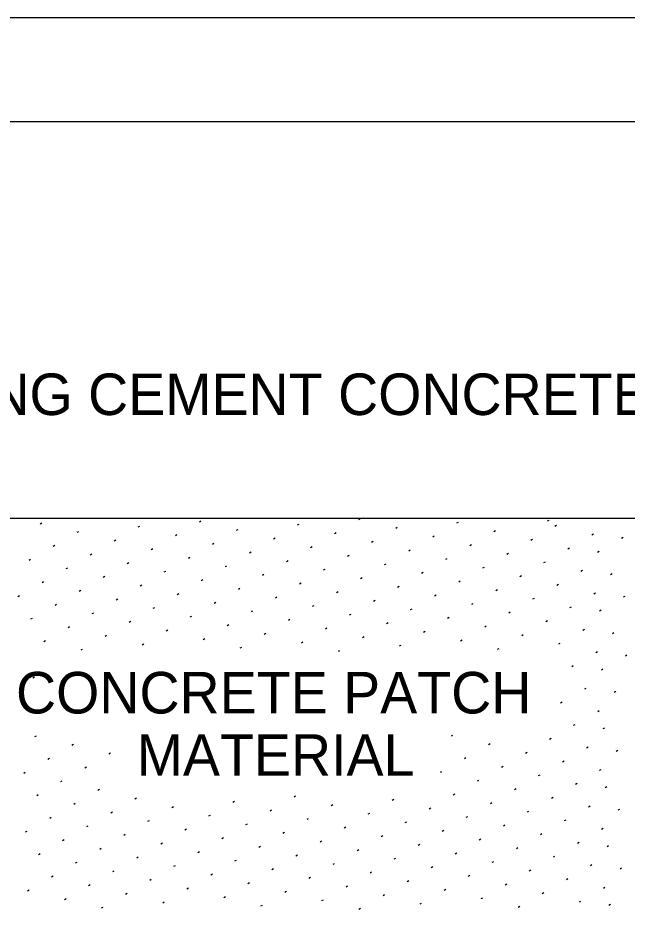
# Model space of a CAD drawing. Extents: x 99862 to 104211, y 98939 to 105076.
# Drawn here: x 102180.3 to 102415, y 104731.9 to 105075.5 of the extents above; entities that cross this region are included whole.
import ezdxf

# ---------------------------------------------------------------- set-up
doc = ezdxf.new("R2010")
doc.units = 0
for name, color, linetype in [('Level 1', 7, 'Continuous'), ('Level 20', 7, 'Continuous'), ('Level 3', 7, 'Continuous')]:
    doc.layers.add(name, color=color, linetype=linetype)

msp = doc.modelspace()

# ---------------------------------------------------------------- linework, layer by layer
at = {"layer": 'Level 1'}
msp.add_line((100264.63, 104882.79), (102495.44, 104882.79), dxfattribs=at)
msp.add_lwpolyline([(99862, 102999.5), (103151, 102999.5), (103151, 105075.5), (99862, 105075.5)], close=True, dxfattribs=at)
msp.add_lwpolyline([(102651.95, 105035.45), (102087.59, 105035.45), (102087.59, 105018.74), (102054.18, 105052.15), (102054.18, 105035.45), (101386.54, 105035.45)], dxfattribs=at)
at = {"layer": 'Level 3'}
for p, q in [((102188.93, 104880.7), (102189.54, 104881.05)), ((102212.46, 104882.74), (102212.56, 104882.79)), ((102226.73, 104879.43), (102227.34, 104879.78)), ((102250.27, 104881.47), (102250.87, 104881.82)), ((102288.07, 104880.21), (102288.68, 104880.56)), ((102311.61, 104882.25), (102312.21, 104882.6)), ((102349.41, 104880.98), (102350.02, 104881.33)), ((102384.34, 104881.75), (102384.95, 104882.1)), ((102387.21, 104879.71), (102387.82, 104880.06)), ((102203.2, 104877.39), (102203.8, 104877.74)), ((102241, 104876.12), (102241.61, 104876.47)), ((102264.54, 104878.16), (102265.14, 104878.51)), ((102302.34, 104876.9), (102302.94, 104877.25)), ((102325.87, 104878.94), (102326.48, 104879.29)), ((102363.68, 104877.67), (102364.28, 104878.02)), ((102401.48, 104876.4), (102402.09, 104876.75)), ((102217.46, 104874.08), (102218.07, 104874.43)), ((102255.27, 104872.81), (102255.87, 104873.16)), ((102278.8, 104874.85), (102279.41, 104875.2)), ((102316.61, 104873.59), (102317.21, 104873.94)), ((102340.14, 104875.63), (102340.75, 104875.98)), ((102354.41, 104872.32), (102355.02, 104872.67)), ((102377.94, 104874.36), (102378.55, 104874.71)), ((102412.88, 104875.13), (102413.48, 104875.48)), ((102193.93, 104872.04), (102194.54, 104872.39)), ((102231.73, 104870.77), (102232.34, 104871.12)), ((102269.54, 104869.5), (102270.14, 104869.85)), ((102293.07, 104871.54), (102293.68, 104871.89)), ((102330.87, 104870.28), (102331.48, 104870.63)), ((102368.68, 104869.01), (102369.28, 104869.36)), ((102392.21, 104871.05), (102392.82, 104871.4)), ((102403.61, 104869.78), (102404.22, 104870.13)), ((102184.66, 104866.69), (102185.27, 104867.04)), ((102208.2, 104868.73), (102208.8, 104869.08)), ((102246, 104867.46), (102246.61, 104867.81)), ((102283.8, 104866.19), (102284.41, 104866.54)), ((102307.34, 104868.24), (102307.94, 104868.59)), ((102345.14, 104866.97), (102345.75, 104867.32)), ((102382.94, 104865.7), (102383.55, 104866.05)), ((102198.93, 104863.38), (102199.54, 104863.73)), ((102222.46, 104865.42), (102223.07, 104865.77)), ((102236.73, 104862.11), (102237.34, 104862.46)), ((102260.27, 104864.15), (102260.87, 104864.5)), ((102298.07, 104862.88), (102298.68, 104863.23)), ((102321.61, 104864.93), (102322.21, 104865.28)), ((102359.41, 104863.66), (102360.02, 104864.01)), ((102397.21, 104862.39), (102397.82, 104862.74)), ((102213.2, 104860.07), (102213.8, 104860.42)), ((102251, 104858.8), (102251.61, 104859.15)), ((102274.54, 104860.84), (102275.14, 104861.19)), ((102312.34, 104859.57), (102312.94, 104859.92)), ((102335.87, 104861.62), (102336.48, 104861.97)), ((102373.68, 104860.35), (102374.28, 104860.7)), ((102408.61, 104861.12), (102409.22, 104861.47)), ((102189.66, 104858.03), (102190.27, 104858.38)), ((102227.46, 104856.76), (102228.07, 104857.11)), ((102265.27, 104855.49), (102265.87, 104855.84)), ((102288.8, 104857.53), (102289.41, 104857.88)), ((102326.61, 104856.27), (102327.21, 104856.62)), ((102350.14, 104858.31), (102350.75, 104858.66)), ((102387.94, 104857.04), (102388.55, 104857.39)), ((102180.39, 104852.68), (102181, 104853.03)), ((102203.93, 104854.72), (102204.54, 104855.07)), ((102241.73, 104853.45), (102242.34, 104853.8)), ((102279.54, 104852.18), (102280.14, 104852.53)), ((102303.07, 104854.22), (102303.68, 104854.57)), ((102340.87, 104852.96), (102341.48, 104853.31)), ((102364.41, 104855), (102365.02, 104855.35)), ((102378.68, 104851.69), (102379.28, 104852.04)), ((102402.21, 104853.73), (102402.82, 104854.08)), ((102413.61, 104852.46), (102414.22, 104852.81)), ((102194.66, 104849.37), (102195.27, 104849.72)), ((102218.2, 104851.41), (102218.8, 104851.76)), ((102256, 104850.14), (102256.61, 104850.49)), ((102293.8, 104848.87), (102294.41, 104849.22)), ((102317.34, 104850.91), (102317.94, 104851.26)), ((102355.14, 104849.65), (102355.75, 104850)), ((102392.94, 104848.38), (102393.55, 104848.73)), ((102208.93, 104846.06), (102209.54, 104846.41)), ((102232.46, 104848.1), (102233.07, 104848.45)), ((102270.27, 104846.83), (102270.87, 104847.18)), ((102308.07, 104845.56), (102308.68, 104845.91)), ((102331.61, 104847.61), (102332.21, 104847.96)), ((102369.41, 104846.34), (102370.02, 104846.69)), ((102404.34, 104847.11), (102404.95, 104847.46)), ((102185.39, 104844.02), (102186, 104844.37)), ((102223.2, 104842.75), (102223.8, 104843.1)), ((102246.73, 104844.79), (102247.34, 104845.14)), ((102261, 104841.48), (102261.61, 104841.83)), ((102284.54, 104843.52), (102285.14, 104843.87)), ((102322.34, 104842.25), (102322.94, 104842.6)), ((102345.87, 104844.3), (102346.48, 104844.65)), ((102383.68, 104843.03), (102384.28, 104843.38)), ((102199.66, 104840.71), (102200.27, 104841.06)), ((102237.46, 104839.44), (102238.07, 104839.79)), ((102275.27, 104838.17), (102275.87, 104838.52)), ((102298.8, 104840.21), (102299.41, 104840.56)), ((102336.61, 104838.94), (102337.21, 104839.29)), ((102360.14, 104840.99), (102360.75, 104841.34)), ((102397.94, 104839.72), (102398.55, 104840.07)), ((102409.34, 104838.45), (102409.95, 104838.8)), ((102190.39, 104835.36), (102191, 104835.71)), ((102213.93, 104837.4), (102214.54, 104837.75)), ((102251.73, 104836.13), (102252.34, 104836.48)), ((102289.54, 104834.86), (102290.14, 104835.21)), ((102313.07, 104836.9), (102313.68, 104837.25)), ((102350.87, 104835.64), (102351.48, 104835.99)), ((102374.41, 104837.68), (102375.02, 104838.03)), ((102204.66, 104832.05), (102205.27, 104832.4)), ((102228.2, 104834.09), (102228.8, 104834.44)), ((102266, 104832.82), (102266.61, 104833.17)), ((102303.8, 104831.55), (102304.41, 104831.9)), ((102327.34, 104833.59), (102327.94, 104833.94)), ((102365.14, 104832.33), (102365.75, 104832.68)), ((102388.68, 104834.37), (102389.28, 104834.72)), ((102402.94, 104831.06), (102403.55, 104831.41)), ((102414.34, 104829.79), (102414.95, 104830.14)), ((102393.68, 104825.71), (102394.28, 104826.06)), ((102405.08, 104824.44), (102405.68, 104824.79)), ((102186.13, 104821.35), (102186.73, 104821.7)), ((102398.68, 104817.05), (102399.28, 104817.4)), ((102410.08, 104815.78), (102410.68, 104816.13)), ((102389.41, 104811.7), (102390.02, 104812.05)), ((102403.68, 104808.39), (102404.28, 104808.74)), ((102394.41, 104803.04), (102395.02, 104803.39)), ((102405.81, 104801.77), (102406.41, 104802.12)), ((102186.86, 104798.68), (102187.46, 104799.03)), ((102347.34, 104798.95), (102347.94, 104799.3)), ((102385.14, 104797.68), (102385.75, 104798.03)), ((102201.13, 104795.37), (102201.73, 104795.72)), ((102361.61, 104795.64), (102362.21, 104795.99)), ((102399.41, 104794.38), (102400.02, 104794.73)), ((102191.86, 104790.02), (102192.46, 104790.37)), ((102215.39, 104792.06), (102216, 104792.41)), ((102352.34, 104790.29), (102352.94, 104790.64)), ((102375.87, 104792.33), (102376.48, 104792.68)), ((102410.81, 104793.11), (102411.41, 104793.46)), ((102206.13, 104786.71), (102206.73, 104787.06)), ((102366.61, 104786.98), (102367.21, 104787.33)), ((102390.14, 104789.02), (102390.75, 104789.37)), ((102182.59, 104784.67), (102183.2, 104785.02)), ((102343.07, 104784.94), (102343.68, 104785.29)), ((102380.87, 104783.67), (102381.48, 104784.02)), ((102404.41, 104785.71), (102405.02, 104786.06)), ((102196.86, 104781.36), (102197.46, 104781.71)), ((102357.34, 104781.63), (102357.94, 104781.98)), ((102395.14, 104780.36), (102395.75, 104780.71)), ((102211.13, 104778.05), (102211.73, 104778.4)), ((102348.07, 104776.28), (102348.68, 104776.63)), ((102371.61, 104778.32), (102372.21, 104778.67)), ((102406.54, 104779.1), (102407.15, 104779.45)), ((102187.59, 104776), (102188.2, 104776.35)), ((102201.86, 104772.7), (102202.46, 104773.05)), ((102225.39, 104774.74), (102226, 104775.09)), ((102263.2, 104773.47), (102263.8, 104773.82)), ((102286.73, 104775.51), (102287.34, 104775.86)), ((102324.54, 104774.24), (102325.14, 104774.59)), ((102362.34, 104772.97), (102362.94, 104773.32)), ((102385.87, 104775.01), (102386.48, 104775.36)), ((102216.13, 104769.39), (102216.73, 104769.74)), ((102239.66, 104771.43), (102240.27, 104771.78)), ((102277.46, 104770.16), (102278.07, 104770.51)), ((102301, 104772.2), (102301.61, 104772.55)), ((102338.8, 104770.93), (102339.41, 104771.28)), ((102376.61, 104769.66), (102377.21, 104770.01)), ((102400.14, 104771.7), (102400.75, 104772.05)), ((102411.54, 104770.44), (102412.15, 104770.79)), ((102192.59, 104767.34), (102193.2, 104767.69)), ((102230.39, 104766.08), (102231, 104766.43)), ((102253.93, 104768.12), (102254.54, 104768.47)), ((102291.73, 104766.85), (102292.34, 104767.2)), ((102315.27, 104768.89), (102315.87, 104769.24)), ((102353.07, 104767.62), (102353.68, 104767.97)), ((102390.87, 104766.35), (102391.48, 104766.7)), ((102206.86, 104764.04), (102207.46, 104764.39)), ((102244.66, 104762.77), (102245.27, 104763.12)), ((102268.2, 104764.81), (102268.8, 104765.16)), ((102306, 104763.54), (102306.61, 104763.89)), ((102329.54, 104765.58), (102330.14, 104765.93)), ((102367.34, 104764.31), (102367.94, 104764.66)), ((102405.14, 104763.04), (102405.75, 104763.39)), ((102183.32, 104761.99), (102183.93, 104762.34)), ((102221.13, 104760.73), (102221.73, 104761.08)), ((102258.93, 104759.46), (102259.54, 104759.81)), ((102282.46, 104761.5), (102283.07, 104761.85)), ((102320.27, 104760.23), (102320.87, 104760.58)), ((102343.8, 104762.27), (102344.41, 104762.62)), ((102358.07, 104758.96), (102358.68, 104759.31)), ((102381.61, 104761), (102382.21, 104761.35)), ((102197.59, 104758.68), (102198.2, 104759.03)), ((102235.39, 104757.42), (102236, 104757.77)), ((102273.2, 104756.15), (102273.8, 104756.5)), ((102296.73, 104758.19), (102297.34, 104758.54)), ((102334.54, 104756.92), (102335.14, 104757.27)), ((102372.34, 104755.65), (102372.94, 104756)), ((102395.87, 104757.69), (102396.48, 104758.04)), ((102407.27, 104756.42), (102407.88, 104756.77)), ((102188.32, 104753.33), (102188.93, 104753.68)), ((102211.86, 104755.37), (102212.46, 104755.72)), ((102226.13, 104752.07), (102226.73, 104752.42)), ((102249.66, 104754.11), (102250.27, 104754.46)), ((102287.46, 104752.84), (102288.07, 104753.19)), ((102311, 104754.88), (102311.61, 104755.23)), ((102348.8, 104753.61), (102349.41, 104753.96)), ((102386.61, 104752.34), (102387.21, 104752.69)), ((102202.59, 104750.02), (102203.2, 104750.37)), ((102240.39, 104748.76), (102241, 104749.11)), ((102263.93, 104750.8), (102264.54, 104751.15)), ((102301.73, 104749.53), (102302.34, 104749.88)), ((102325.27, 104751.57), (102325.87, 104751.92)), ((102363.07, 104750.3), (102363.68, 104750.65)), ((102400.87, 104749.03), (102401.48, 104749.38)), ((102216.86, 104746.71), (102217.46, 104747.06)), ((102254.66, 104745.45), (102255.27, 104745.8)), ((102278.2, 104747.49), (102278.8, 104747.84)), ((102316, 104746.22), (102316.61, 104746.57)), ((102339.54, 104748.26), (102340.14, 104748.61)), ((102377.34, 104746.99), (102377.94, 104747.34)), ((102412.27, 104747.76), (102412.88, 104748.11)), ((102193.32, 104744.67), (102193.93, 104745.02)), ((102231.13, 104743.41), (102231.73, 104743.76)), ((102268.93, 104742.14), (102269.54, 104742.49)), ((102292.46, 104744.18), (102293.07, 104744.53)), ((102330.27, 104742.91), (102330.87, 104743.26)), ((102353.8, 104744.95), (102354.41, 104745.3)), ((102391.61, 104743.68), (102392.21, 104744.03)), ((102184.06, 104739.32), (102184.66, 104739.67)), ((102207.59, 104741.36), (102208.2, 104741.71)), ((102245.39, 104740.1), (102246, 104740.45)), ((102283.2, 104738.83), (102283.8, 104739.18)), ((102306.73, 104740.87), (102307.34, 104741.22)), ((102344.54, 104739.6), (102345.14, 104739.95)), ((102368.07, 104741.64), (102368.68, 104741.99)), ((102382.34, 104738.33), (102382.94, 104738.68)), ((102405.87, 104740.37), (102406.48, 104740.72)), ((102198.32, 104736.01), (102198.93, 104736.36)), ((102221.86, 104738.05), (102222.46, 104738.4)), ((102259.66, 104736.79), (102260.27, 104737.14)), ((102297.46, 104735.52), (102298.07, 104735.87)), ((102321, 104737.56), (102321.61, 104737.91)), ((102358.8, 104736.29), (102359.41, 104736.64)), ((102396.61, 104735.02), (102397.21, 104735.37)), ((102212.59, 104732.7), (102213.2, 104733.05)), ((102236.13, 104734.74), (102236.73, 104735.09)), ((102273.93, 104733.48), (102274.54, 104733.83)), ((102311.73, 104732.21), (102312.34, 104732.56)), ((102335.27, 104734.25), (102335.87, 104734.6)), ((102373.07, 104732.98), (102373.68, 104733.33)), ((102408, 104733.75), (102408.61, 104734.1))]:
    msp.add_line(p, q, dxfattribs=at)

# ---------------------------------------------------------------- texts
at = {"layer": 'Level 20'}
for s, p in [('EXISTING CEMENT CONCRETE PAVEMENT', (102101.58, 104922.53)), ('CONCRETE PATCH', (102179.62, 104807.6)), ('MATERIAL', (102226.1, 104783.6))]:
    msp.add_text(s, height=16, dxfattribs=at).set_placement(p)

doc.saveas('drawing.dxf')
